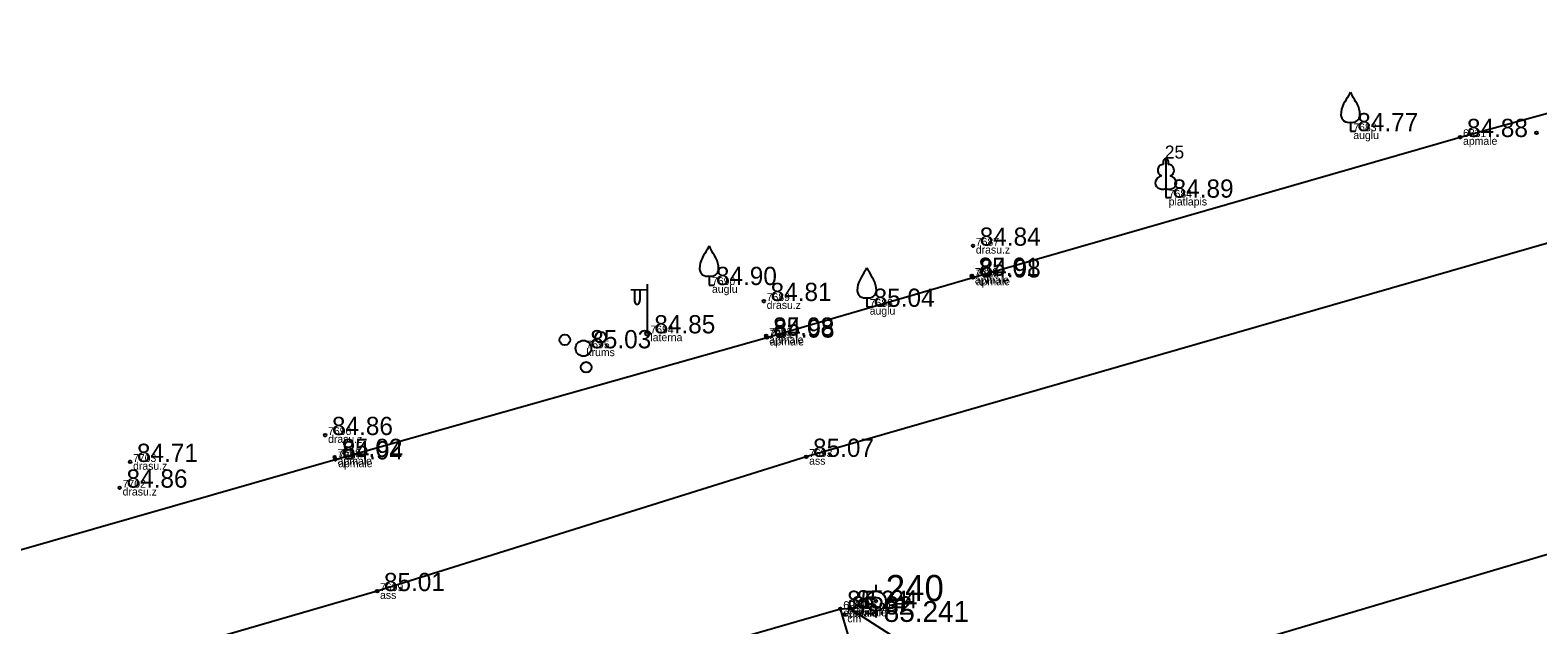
# Model space of a CAD drawing. Extents: x 614911 to 615803, y 262110 to 264311.
# Drawn here: x 615140.5 to 615198.4, y 262530.5 to 262553.3 of the extents above; entities that cross this region are included whole.
import ezdxf

# ---------------------------------------------------------------- set-up
doc = ezdxf.new("R2010")
doc.units = 0
for name, color, linetype in [('Level 1', 7, 'Continuous'), ('Level 19', 7, 'Continuous'), ('Level 37', 7, 'Continuous'), ('Level 44', 7, 'Continuous'), ('Level 53', 7, 'Continuous'), ('Level 54', 7, 'Continuous'), ('Level 57', 7, 'Continuous'), ('Level 58', 7, 'Continuous')]:
    doc.layers.add(name, color=color, linetype=linetype)

msp = doc.modelspace()

# ---------------------------------------------------------------- linework, layer by layer
at = {"layer": 'Level 1'}
for p, q in [((615191.187, 262549.789), (615191.187, 262549.437)), ((615191.187, 262549.437), (615191.387, 262549.437)), ((615184.098, 262547.235), (615184.098, 262546.888)), ((615184.098, 262546.888), (615184.298, 262546.888)), ((615166.562, 262543.886), (615166.562, 262543.534)), ((615166.562, 262543.534), (615166.762, 262543.534)), ((615172.617, 262543.051), (615172.617, 262542.699)), ((615172.617, 262542.699), (615172.817, 262542.699))]:
    msp.add_line(p, q, dxfattribs=at)
for points in [[(615184.098, 262548.388), (615184.098, 262547.235)], [(615184.188, 262548.156), (615184.187, 262548.157)]]:
    msp.add_lwpolyline(points, dxfattribs=at)
for centre, radius in [((615161.024, 262541.431), 0.204), ((615162.399, 262541.532), 0.207), ((615161.738, 262541.107), 0.301), ((615161.841, 262540.379), 0.205)]:
    msp.add_circle(centre, radius, dxfattribs=at)
for centre, radius, start, end in [((615203.812, 262543.041), 14.88, 148.48442, 149.99014), ((615190.77, 262551.075), 0.439, 324.38368, 341.71196), ((615191.604, 262551.075), 0.439, 198.28804, 215.61632), ((615178.562, 262543.041), 14.88, 30.00986, 31.51558), ((615191.711, 262550.062), 0.89, 151.75703, 179.91384), ((615190.663, 262550.062), 0.89, 0.08616, 28.24297), ((615191.111, 262550.068), 0.29, 181.07816, 285.2823), ((615191.263, 262550.068), 0.29, 254.7177, 358.92184), ((615166.145, 262545.172), 0.439, 324.38368, 341.71196), ((615166.979, 262545.172), 0.439, 198.28804, 215.61632), ((615167.086, 262544.159), 0.89, 151.75703, 179.91384), ((615179.187, 262537.138), 14.88, 148.48442, 149.99014), ((615153.937, 262537.138), 14.88, 30.00986, 31.51558), ((615166.038, 262544.159), 0.89, 0.08616, 28.24297), ((615166.486, 262544.165), 0.29, 181.07816, 285.2823), ((615166.638, 262544.165), 0.29, 254.7177, 358.92184), ((615185.242, 262536.303), 14.88, 148.48442, 149.99014), ((615172.2, 262544.337), 0.439, 324.38368, 341.71196), ((615173.034, 262544.337), 0.439, 198.28804, 215.61632), ((615159.992, 262536.303), 14.88, 30.00986, 31.51558), ((615173.141, 262543.324), 0.89, 151.75703, 179.91384), ((615172.541, 262543.33), 0.29, 181.07816, 285.2823), ((615172.693, 262543.33), 0.29, 254.7177, 358.92184), ((615172.093, 262543.324), 0.89, 0.08616, 28.24297)]:
    msp.add_arc(centre, radius, start, end, dxfattribs=at)
for centre, major_axis, ratio, start_param, end_param in [((615183.97, 262547.943), (-0.039, -0.212), 0.861323, 3.141593, 6.283185), ((615184.098, 262548.238), (0, -0.15), 0.707107, 3.14537, 5.287485), ((615184.098, 262548.238), (0, -0.15), 0.707107, 0.995701, 3.137816), ((615184.226, 262547.943), (0.039, -0.212), 0.861323, 0, 3.141593), ((615184.008, 262547.481), (0.307, 0.095), 0.814445, 1.570796, 4.752015), ((615184.188, 262547.481), (-0.307, 0.095), 0.814445, 1.531171, 4.712389)]:
    msp.add_ellipse(centre, major_axis=major_axis, ratio=ratio, start_param=start_param, end_param=end_param, dxfattribs=at)
at = {"layer": 'Level 19'}
for p, q in [((615172.972, 262531.784), (615172.972, 262532.034)), ((615172.347, 262531.409), (615172.597, 262531.409)), ((615173.347, 262531.409), (615173.597, 262531.409)), ((615172.972, 262530.784), (615172.972, 262531.034))]:
    msp.add_line(p, q, dxfattribs=at)
for radius in [0.375, 0.05]:
    msp.add_circle((615172.972, 262531.409), radius, dxfattribs=at)
at = {"layer": 'Level 37'}
for points in [[(615134.751, 262536.316), (615136.666, 262532.387), (615152.21, 262536.845), (615168.777, 262541.517), (615176.69, 262543.827), (615195.4, 262549.214), (615198.892, 262550.172), (615209.293, 262553.06), (615211.306, 262553.645), (615214.425, 262554.554), (615214.157, 262556.702), (615205.474, 262561.046), (615198.438, 262564.498), (615187.2, 262570.428), (615171.016, 262579.803)], [(615223.546, 262552.282), (615170.292, 262536.941), (615153.815, 262531.791), (615121.081, 262522.293), (615097.679, 262519.819), (615079.491, 262520.592), (615062.627, 262523.82), (615033.227, 262532.662), (615019.453, 262538.139)], [(615199.356, 262533.372), (615178.227, 262527.111), (615173.238, 262525.598), (615171.602, 262531.108), (615171.962, 262531.125), (615178.227, 262527.111)], [(615135.871, 262487.756), (615129.672, 262489.428), (615127.391, 262497.412), (615121.959, 262516.828), (615156.135, 262526.657), (615171.602, 262531.108)]]:
    msp.add_lwpolyline(points, dxfattribs=at)
at = {"layer": 'Level 44'}
for p, q in [((615164.197, 262543.347), (615163.562, 262543.342)), ((615163.697, 262543.343), (615163.697, 262542.951)), ((615163.907, 262543.345), (615163.907, 262542.951)), ((615164.197, 262541.68), (615164.197, 262543.563))]:
    msp.add_line(p, q, dxfattribs=at)
msp.add_circle((615164.197, 262541.68), 0.09, dxfattribs=at)
msp.add_ellipse((615163.802, 262542.951), major_axis=(0, 0.151), ratio=0.695971, start_param=1.570796, end_param=4.712389, dxfattribs=at)
at = {"layer": 'Level 57'}
for centre in [(615195.4, 262549.214), (615198.328, 262549.376), (615176.692, 262545.043), (615176.65, 262543.887), (615176.69, 262543.827), (615168.661, 262542.921), (615168.756, 262541.592), (615168.777, 262541.517), (615151.82, 262537.779), (615152.185, 262536.937), (615152.21, 262536.845), (615170.292, 262536.941), (615144.332, 262536.747), (615143.932, 262535.759), (615153.815, 262531.791), (615171.602, 262531.108), (615171.962, 262531.125), (615171.758, 262530.893)]:
    msp.add_circle(centre, 0.05, dxfattribs=at)
at = {"layer": 'Level 58'}
for centre in [(615195.4, 262549.214), (615198.328, 262549.376), (615176.692, 262545.043), (615176.65, 262543.887), (615176.69, 262543.827), (615168.661, 262542.921), (615168.756, 262541.592), (615168.777, 262541.517), (615151.82, 262537.779), (615152.185, 262536.937), (615152.21, 262536.845), (615170.292, 262536.941), (615144.332, 262536.747), (615143.932, 262535.759), (615153.815, 262531.791), (615171.602, 262531.108), (615171.962, 262531.125), (615171.758, 262530.893)]:
    msp.add_circle(centre, 0.05, dxfattribs=at)

# ---------------------------------------------------------------- texts
at = {"layer": 'Level 1'}
msp.add_text(' 25', height=0.5, dxfattribs=at).set_placement((615183.873, 262548.388))
at = {"layer": 'Level 19'}
for s, height, p in [(' 240', 1, (615172.972, 262531.409)), (' 85.241', 0.8, (615172.972, 262530.609))]:
    msp.add_text(s, height=height, dxfattribs=at).set_placement(p)
at = {"layer": 'Level 53'}
for s, p in [(' auglu', (615191.187, 262549.137)), (' apmale', (615195.4, 262548.914)), (' platlapis', (615184.098, 262546.588)), (' drasu.z', (615176.692, 262544.743)), (' apmale', (615176.65, 262543.587)), (' apmale', (615176.69, 262543.527)), (' auglu', (615166.562, 262543.234)), (' drasu.z', (615168.661, 262542.621)), (' auglu', (615172.617, 262542.399)), (' laterna', (615164.197, 262541.38)), (' apmale', (615168.756, 262541.292)), (' apmale', (615168.777, 262541.217)), (' krums', (615161.738, 262540.807)), (' drasu.z', (615151.82, 262537.479)), (' apmale', (615152.185, 262536.637)), (' ass', (615170.292, 262536.641)), (' drasu.z', (615144.332, 262536.447)), (' apmale', (615152.21, 262536.545)), (' drasu.z', (615143.932, 262535.459)), (' ass', (615153.815, 262531.491)), (' apmale', (615171.602, 262530.808)), (' apmale', (615171.962, 262530.825)), (' gp', (615172.972, 262531.109)), (' pp', (615172.972, 262531.109)), (' cm', (615171.758, 262530.593))]:
    msp.add_text(s, height=0.3, dxfattribs=at).set_placement(p)
at = {"layer": 'Level 54'}
for s, p in [(' 7683', (615191.187, 262549.437)), (' 6831', (615195.4, 262549.214)), (' 7684', (615184.098, 262546.888)), (' 7687', (615176.692, 262545.043)), (' 7690', (615166.562, 262543.534)), (' 7686', (615176.65, 262543.887)), (' 7685', (615176.69, 262543.827)), (' 7689', (615168.661, 262542.921)), (' 7688', (615172.617, 262542.699)), (' 7694', (615164.197, 262541.68)), (' 7692', (615168.756, 262541.592)), (' 7691', (615168.777, 262541.517)), (' 7695', (615161.738, 262541.107)), (' 7696', (615151.82, 262537.779)), (' 7703', (615144.332, 262536.747)), (' 7698', (615152.185, 262536.937)), (' 7697', (615152.21, 262536.845)), (' 7693', (615170.292, 262536.941)), (' 7702', (615143.932, 262535.759)), (' 7699', (615153.815, 262531.791)), (' 6900', (615171.602, 262531.108)), (' 6902', (615171.758, 262530.893)), (' 6901', (615171.962, 262531.125))]:
    msp.add_text(s, height=0.3, dxfattribs=at).set_placement(p)
at = {"layer": 'Level 58'}
for s, p in [(' 84.77', (615191.187, 262549.437)), (' 84.88', (615195.4, 262549.214)), (' 84.89', (615184.098, 262546.888)), (' 84.84', (615176.692, 262545.043)), (' 85.01', (615176.65, 262543.887)), (' 84.98', (615176.69, 262543.827)), (' 84.90', (615166.562, 262543.534)), (' 84.81', (615168.661, 262542.921)), (' 85.04', (615172.617, 262542.699)), (' 84.85', (615164.197, 262541.68)), (' 85.08', (615168.756, 262541.592)), (' 84.98', (615168.777, 262541.517)), (' 85.03', (615161.738, 262541.107)), (' 84.86', (615151.82, 262537.779)), (' 84.71', (615144.332, 262536.747)), (' 85.02', (615152.185, 262536.937)), (' 84.94', (615152.21, 262536.845)), (' 85.07', (615170.292, 262536.941)), (' 84.86', (615143.932, 262535.759)), (' 85.01', (615153.815, 262531.791)), (' 85.24', (615171.602, 262531.108)), (' 85.24', (615171.962, 262531.125)), (' 85.32', (615171.758, 262530.893))]:
    msp.add_text(s, height=0.7, dxfattribs=at).set_placement(p)

doc.saveas('drawing.dxf')
